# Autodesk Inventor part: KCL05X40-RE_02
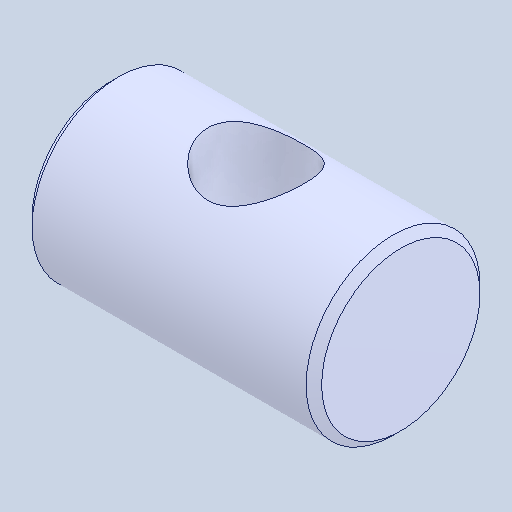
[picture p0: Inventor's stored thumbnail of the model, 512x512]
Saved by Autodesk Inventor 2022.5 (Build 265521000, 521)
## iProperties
Created: 2024-08
Part Number: KCL05X40-RE_02
Material: 一般
Document SubType Name: Modeling
Designer: ImaoCorp
Density: 1 g/cm^3
Appearance: 既定
Author: ImaoCorp
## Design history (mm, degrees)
feature "KCL05X40-RE_02"
node "ソリッド1"
